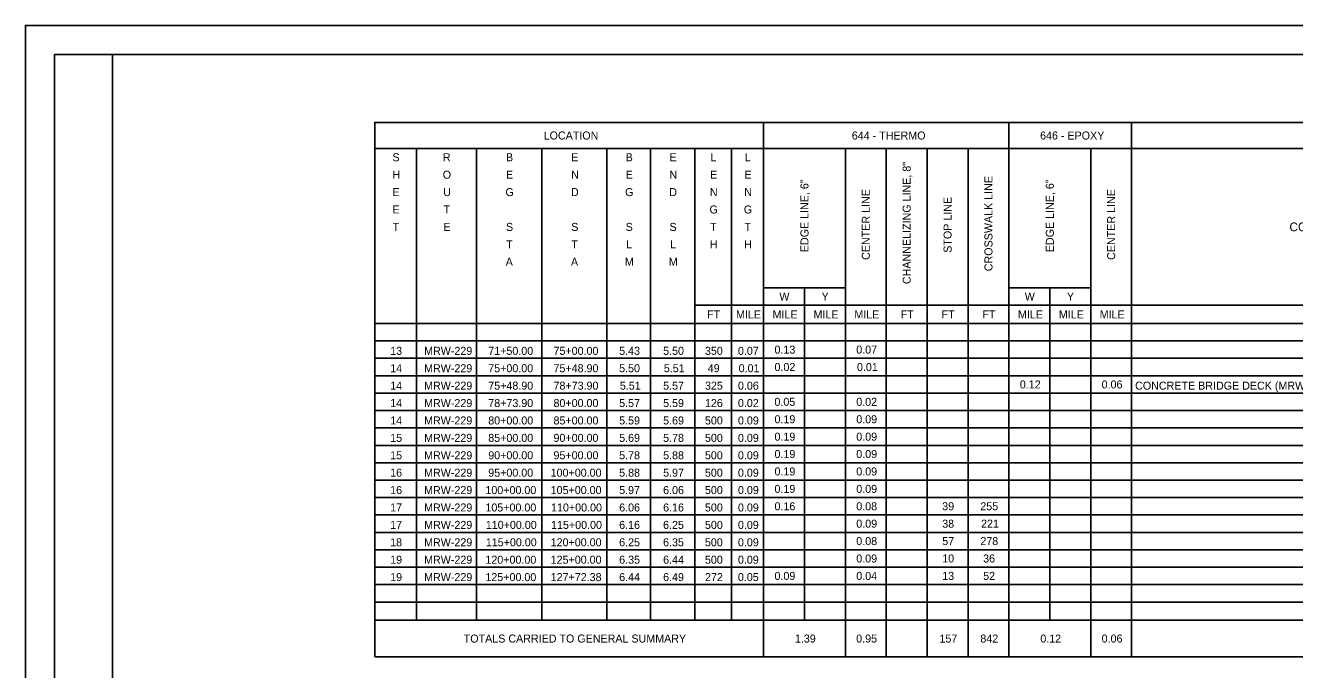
# Model space of a CAD drawing. Extents: x 0 to 34, y 0 to 22.
# Drawn here: x 0 to 21.88, y 10.9 to 22 of the extents above; entities that cross this region are included whole.
import ezdxf

# ---------------------------------------------------------------- set-up
doc = ezdxf.new("R2010")
doc.units = 0
for name, color, linetype in [('Default', 7, 'Continuous'), ('SH_Border', 7, 'Continuous'), ('SH_Cut_Line', 7, 'Continuous')]:
    doc.layers.add(name, color=color, linetype=linetype)

msp = doc.modelspace()

# ---------------------------------------------------------------- linework, layer by layer
at = {"layer": 'Default'}
for p, q in [((6.022, 20.327), (25.597, 20.327)), ((6.022, 20.327), (6.022, 11.117)), ((12.727, 20.327), (12.727, 11.117)), ((16.957, 20.327), (16.957, 11.117)), ((19.072, 20.327), (19.072, 11.117)), ((6.022, 19.877), (25.597, 19.877)), ((6.742, 19.877), (6.742, 11.747)), ((7.777, 19.877), (7.777, 11.747)), ((8.902, 19.877), (8.902, 11.747)), ((10.027, 19.877), (10.027, 11.747)), ((10.777, 19.877), (10.777, 11.747)), ((11.542, 19.877), (11.542, 11.747)), ((12.172, 19.877), (12.172, 11.747)), ((14.137, 19.877), (14.137, 11.117)), ((14.842, 19.877), (14.842, 11.117)), ((15.547, 19.877), (15.547, 11.117)), ((16.252, 19.877), (16.252, 11.117)), ((18.367, 19.877), (18.367, 11.117)), ((12.727, 17.477), (14.137, 17.477)), ((13.432, 17.477), (13.432, 11.747)), ((16.957, 17.477), (18.367, 17.477)), ((17.662, 17.477), (17.662, 11.747)), ((11.542, 17.177), (25.597, 17.177)), ((6.022, 16.862), (25.597, 16.862)), ((6.022, 16.562), (25.597, 16.562)), ((6.022, 16.262), (25.597, 16.262)), ((6.022, 15.962), (25.597, 15.962)), ((6.022, 15.662), (25.597, 15.662)), ((6.022, 15.362), (25.597, 15.362)), ((6.022, 15.062), (25.597, 15.062)), ((6.022, 14.762), (25.597, 14.762)), ((6.022, 14.462), (25.597, 14.462)), ((6.022, 14.162), (25.597, 14.162)), ((6.022, 13.862), (25.597, 13.862)), ((6.022, 13.562), (25.597, 13.562)), ((6.022, 13.262), (25.597, 13.262)), ((6.022, 12.962), (25.597, 12.962)), ((6.022, 12.662), (25.597, 12.662)), ((6.022, 12.362), (25.597, 12.362)), ((6.022, 12.062), (25.597, 12.062)), ((6.022, 11.747), (25.597, 11.747)), ((6.022, 11.117), (25.597, 11.117))]:
    msp.add_line(p, q, dxfattribs=at)
for points in [[(6.022, 20.327), (6.022, 20.327), (6.022, 20.027), (6.022, 20.027)], [(6.022, 20.327), (6.022, 20.327), (6.022, 20.027), (6.022, 20.027)], [(6.022, 20.327), (6.022, 20.327), (6.022, 20.027), (6.022, 20.027)], [(6.022, 20.327), (6.022, 20.327), (6.022, 20.027), (6.022, 20.027)], [(6.022, 20.327), (6.022, 20.327), (6.022, 20.027), (6.022, 20.027)], [(6.022, 20.327), (6.022, 20.327), (6.022, 20.027), (6.022, 20.027)], [(6.022, 20.327), (6.022, 20.327), (6.022, 20.027), (6.022, 20.027)], [(6.022, 20.327), (6.022, 20.327), (6.022, 20.027), (6.022, 20.027)], [(6.022, 20.327), (6.022, 20.327), (6.022, 20.027), (6.022, 20.027)], [(6.022, 20.327), (6.022, 20.327), (6.022, 20.012), (6.022, 20.012)], [(6.022, 20.327), (6.022, 20.327), (6.022, 20.027), (6.022, 20.027)], [(6.022, 20.327), (6.022, 20.327), (6.022, 20.027), (6.022, 20.027)], [(6.022, 20.327), (6.022, 20.327), (6.022, 20.027), (6.022, 20.027)], [(6.022, 20.327), (6.022, 20.327), (6.022, 20.027), (6.022, 20.027)], [(6.022, 20.327), (6.022, 20.327), (6.022, 20.027), (6.022, 20.027)], [(6.022, 20.327), (6.022, 20.327), (6.022, 20.027), (6.022, 20.027)], [(6.022, 20.327), (6.022, 20.327), (6.022, 20.027), (6.022, 20.027)], [(6.022, 20.327), (6.022, 20.327), (6.022, 20.027), (6.022, 20.027)], [(6.022, 20.327), (6.022, 20.327), (6.022, 20.027), (6.022, 20.027)], [(6.022, 20.327), (6.022, 20.327), (6.022, 20.027), (6.022, 20.027)], [(6.022, 20.327), (6.022, 20.327), (6.022, 20.027), (6.022, 20.027)], [(6.022, 20.327), (6.022, 20.327), (6.022, 20.027), (6.022, 20.027)], [(6.022, 20.327), (6.022, 20.327), (6.022, 20.027), (6.022, 20.027)], [(6.022, 20.327), (6.022, 20.327), (6.022, 20.027), (6.022, 20.027)], [(6.022, 20.327), (6.022, 20.327), (6.022, 20.027), (6.022, 20.027)], [(6.022, 20.327), (6.022, 20.327), (6.022, 20.027), (6.022, 20.027)], [(6.022, 20.327), (6.022, 20.327), (6.022, 20.012), (6.022, 20.012)]]:
    msp.add_lwpolyline(points, close=True, dxfattribs=at)
at = {"layer": 'SH_Border'}
for points in [[(0.5, 21.5), (1.5, 21.5), (1.5, 0.5), (0.5, 0.5)], [(1.5, 21.5), (33.5, 21.5), (33.5, 0.5), (1.5, 0.5)]]:
    msp.add_lwpolyline(points, close=True, dxfattribs=at)
at = {"layer": 'SH_Cut_Line'}
msp.add_lwpolyline([(0, 0), (34, 0), (34, 22), (0, 22)], close=True, dxfattribs=at)

# ---------------------------------------------------------------- texts
at = {"layer": 'Default'}
for s, height, p in [('LOCATION', 0.138, (8.935, 20.033)), ('644 - THERMO', 0.138, (14.248, 20.033)), ('646 - EPOXY', 0.138, (17.494, 20.033)), ('S', 0.138, (6.329, 19.658)), ('R', 0.138, (7.198, 19.658)), ('B', 0.138, (8.286, 19.658)), ('E', 0.138, (9.411, 19.658)), ('B', 0.138, (10.349, 19.658)), ('E', 0.138, (11.106, 19.658)), ('L', 0.138, (11.812, 19.658)), ('L', 0.138, (12.404, 19.658)), ('H', 0.138, (6.326, 19.358)), ('O', 0.138, (7.196, 19.358)), ('E', 0.138, (8.286, 19.358)), ('N', 0.138, (9.409, 19.358)), ('E', 0.138, (10.349, 19.358)), ('N', 0.138, (11.104, 19.358)), ('E', 0.138, (11.804, 19.358)), ('E', 0.138, (12.396, 19.358)), ('E', 0.138, (6.329, 19.058)), ('U', 0.138, (7.204, 19.058)), ('G', 0.138, (8.277, 19.058)), ('D', 0.138, (9.406, 19.058)), ('G', 0.138, (10.34, 19.058)), ('D', 0.138, (11.101, 19.058)), ('N', 0.138, (11.801, 19.058)), ('N', 0.138, (12.394, 19.058)), ('E', 0.138, (6.329, 18.758)), ('T', 0.138, (7.208, 18.758)), ('G', 0.138, (11.795, 18.758)), ('G', 0.138, (12.387, 18.758)), ('COMMENTS', 0.1518, (21.793, 18.451)), ('T', 0.138, (6.331, 18.458)), ('E', 0.138, (7.206, 18.458)), ('S', 0.138, (8.286, 18.458)), ('S', 0.138, (9.411, 18.458)), ('S', 0.138, (10.349, 18.458)), ('S', 0.138, (11.106, 18.458)), ('T', 0.138, (11.806, 18.458)), ('T', 0.138, (12.398, 18.458)), ('T', 0.138, (8.288, 18.158)), ('T', 0.138, (9.413, 18.158)), ('L', 0.138, (10.357, 18.158)), ('L', 0.138, (11.114, 18.158)), ('H', 0.138, (11.801, 18.158)), ('H', 0.138, (12.394, 18.158)), ('A', 0.138, (8.281, 17.858)), ('A', 0.138, (9.406, 17.858)), ('M', 0.138, (10.336, 17.858)), ('M', 0.138, (11.094, 17.858)), ('W', 0.138, (12.999, 17.258)), ('Y', 0.138, (13.727, 17.258)), ('W', 0.138, (17.229, 17.258)), ('Y', 0.138, (17.957, 17.258)), ('FT', 0.138, (11.753, 16.95)), ('MILE', 0.138, (12.252, 16.95)), ('MILE', 0.138, (12.882, 16.95)), ('MILE', 0.138, (13.587, 16.95)), ('MILE', 0.138, (14.292, 16.95)), ('FT', 0.138, (15.09, 16.95)), ('FT', 0.138, (15.795, 16.95)), ('FT', 0.138, (16.5, 16.95)), ('MILE', 0.138, (17.112, 16.95)), ('MILE', 0.138, (17.817, 16.95)), ('MILE', 0.138, (18.522, 16.95)), ('13', 0.138, (6.289, 16.322)), ('MRW-229', 0.138, (6.874, 16.322)), ('71+50.00', 0.138, (7.98, 16.322)), ('75+00.00', 0.138, (9.105, 16.322)), ('5.43', 0.138, (10.237, 16.322)), ('5.50', 0.138, (10.995, 16.322)), ('350', 0.138, (11.716, 16.322)), ('0.07', 0.138, (12.285, 16.322)), ('0.13', 0.138, (12.915, 16.343)), ('0.07', 0.138, (14.325, 16.343)), ('14', 0.138, (6.29, 16.022)), ('MRW-229', 0.138, (6.874, 16.022)), ('75+00.00', 0.138, (7.98, 16.022)), ('75+48.90', 0.138, (9.105, 16.022)), ('5.50', 0.138, (10.237, 16.022)), ('5.51', 0.138, (11.007, 16.022)), ('49', 0.138, (11.764, 16.022)), ('0.01', 0.138, (12.297, 16.022)), ('0.02', 0.138, (12.915, 16.043)), ('0.01', 0.138, (14.337, 16.043)), ('14', 0.138, (6.29, 15.722)), ('MRW-229', 0.138, (6.874, 15.722)), ('75+48.90', 0.138, (7.98, 15.722)), ('78+73.90', 0.138, (9.105, 15.722)), ('5.51', 0.138, (10.249, 15.722)), ('5.57', 0.138, (10.995, 15.722)), ('325', 0.138, (11.716, 15.722)), ('0.06', 0.138, (12.285, 15.722)), ('0.12', 0.138, (17.145, 15.743)), ('0.06', 0.138, (18.555, 15.743)), ('CONCRETE BRIDGE DECK (MRW-71-3.86, SR 229 OVER I-71)', 0.138, (19.132, 15.722)), ('14', 0.138, (6.29, 15.422)), ('MRW-229', 0.138, (6.874, 15.422)), ('78+73.90', 0.138, (7.98, 15.422)), ('80+00.00', 0.138, (9.105, 15.422)), ('5.57', 0.138, (10.237, 15.422)), ('5.59', 0.138, (10.995, 15.422)), ('126', 0.138, (11.716, 15.422)), ('0.02', 0.138, (12.285, 15.422)), ('0.05', 0.138, (12.914, 15.443)), ('0.02', 0.138, (14.325, 15.443)), ('14', 0.138, (6.29, 15.122)), ('MRW-229', 0.138, (6.874, 15.122)), ('80+00.00', 0.138, (7.98, 15.122)), ('85+00.00', 0.138, (9.105, 15.122)), ('5.59', 0.138, (10.237, 15.122)), ('5.69', 0.138, (10.995, 15.122)), ('500', 0.138, (11.716, 15.122)), ('0.09', 0.138, (12.285, 15.122)), ('0.19', 0.138, (12.915, 15.143)), ('0.09', 0.138, (14.325, 15.143)), ('15', 0.138, (6.289, 14.822)), ('MRW-229', 0.138, (6.874, 14.822)), ('85+00.00', 0.138, (7.98, 14.822)), ('90+00.00', 0.138, (9.105, 14.822)), ('5.69', 0.138, (10.237, 14.822)), ('5.78', 0.138, (10.995, 14.822)), ('500', 0.138, (11.716, 14.822)), ('0.09', 0.138, (12.285, 14.822)), ('0.19', 0.138, (12.915, 14.843)), ('0.09', 0.138, (14.325, 14.843)), ('MRW-229', 0.138, (6.874, 14.522)), ('90+00.00', 0.138, (7.98, 14.522)), ('95+00.00', 0.138, (9.105, 14.522)), ('5.78', 0.138, (10.237, 14.522)), ('5.88', 0.138, (10.995, 14.522)), ('500', 0.138, (11.716, 14.522)), ('0.09', 0.138, (12.285, 14.522)), ('0.19', 0.138, (12.915, 14.543)), ('0.09', 0.138, (14.325, 14.543)), ('15', 0.138, (6.289, 14.522)), ('16', 0.138, (6.289, 14.222)), ('MRW-229', 0.138, (6.874, 14.222)), ('95+00.00', 0.138, (7.98, 14.222)), ('100+00.00', 0.138, (9.056, 14.222)), ('5.88', 0.138, (10.237, 14.222)), ('5.97', 0.138, (10.995, 14.222)), ('500', 0.138, (11.716, 14.222)), ('0.09', 0.138, (12.285, 14.222)), ('0.19', 0.138, (12.915, 14.243)), ('0.09', 0.138, (14.325, 14.243)), ('16', 0.138, (6.289, 13.922)), ('MRW-229', 0.138, (6.874, 13.922)), ('100+00.00', 0.138, (7.931, 13.922)), ('105+00.00', 0.138, (9.056, 13.922)), ('5.97', 0.138, (10.237, 13.922)), ('6.06', 0.138, (10.995, 13.922)), ('500', 0.138, (11.716, 13.922)), ('0.09', 0.138, (12.285, 13.922)), ('0.19', 0.138, (12.915, 13.943)), ('0.09', 0.138, (14.325, 13.943)), ('17', 0.138, (6.289, 13.622)), ('MRW-229', 0.138, (6.874, 13.622)), ('105+00.00', 0.138, (7.931, 13.622)), ('110+00.00', 0.138, (9.063, 13.622)), ('6.06', 0.138, (10.237, 13.622)), ('6.16', 0.138, (10.995, 13.622)), ('500', 0.138, (11.716, 13.622)), ('0.09', 0.138, (12.285, 13.622)), ('0.16', 0.138, (12.915, 13.643)), ('0.08', 0.138, (14.325, 13.643)), ('39', 0.138, (15.807, 13.643)), ('255', 0.138, (16.463, 13.643)), ('17', 0.138, (6.289, 13.322)), ('MRW-229', 0.138, (6.874, 13.322)), ('110+00.00', 0.138, (7.938, 13.322)), ('115+00.00', 0.138, (9.063, 13.322)), ('6.16', 0.138, (10.237, 13.322)), ('6.25', 0.138, (10.994, 13.322)), ('500', 0.138, (11.716, 13.322)), ('0.09', 0.138, (12.285, 13.322)), ('0.09', 0.138, (14.325, 13.343)), ('38', 0.138, (15.807, 13.343)), ('221', 0.138, (16.476, 13.343)), ('18', 0.138, (6.289, 13.022)), ('MRW-229', 0.138, (6.874, 13.022)), ('115+00.00', 0.138, (7.938, 13.022)), ('120+00.00', 0.138, (9.056, 13.022)), ('6.25', 0.138, (10.237, 13.022)), ('6.35', 0.138, (10.994, 13.022)), ('500', 0.138, (11.716, 13.022)), ('0.09', 0.138, (12.285, 13.022)), ('0.08', 0.138, (14.325, 13.043)), ('57', 0.138, (15.807, 13.043)), ('278', 0.138, (16.464, 13.043)), ('19', 0.138, (6.289, 12.722)), ('MRW-229', 0.138, (6.874, 12.722)), ('120+00.00', 0.138, (7.931, 12.722)), ('125+00.00', 0.138, (9.056, 12.722)), ('6.35', 0.138, (10.237, 12.722)), ('6.44', 0.138, (10.995, 12.722)), ('500', 0.138, (11.716, 12.722)), ('0.09', 0.138, (12.285, 12.722)), ('0.09', 0.138, (14.325, 12.743)), ('10', 0.138, (15.807, 12.743)), ('36', 0.138, (16.512, 12.743)), ('19', 0.138, (6.289, 12.422)), ('MRW-229', 0.138, (6.874, 12.422)), ('125+00.00', 0.138, (7.931, 12.422)), ('127+72.38', 0.138, (9.056, 12.422)), ('6.44', 0.138, (10.237, 12.422)), ('6.49', 0.138, (10.995, 12.422)), ('272', 0.138, (11.717, 12.422)), ('0.05', 0.138, (12.284, 12.422)), ('0.09', 0.138, (12.915, 12.443)), ('0.04', 0.138, (14.325, 12.443)), ('13', 0.138, (15.807, 12.443)), ('52', 0.138, (16.513, 12.443)), ('TOTALS CARRIED TO GENERAL SUMMARY', 0.138, (7.557, 11.363)), ('1.39', 0.138, (13.267, 11.363)), ('0.95', 0.138, (14.324, 11.363)), ('157', 0.138, (15.759, 11.363)), ('842', 0.138, (16.464, 11.363)), ('0.12', 0.138, (17.498, 11.363)), ('0.06', 0.138, (18.555, 11.363))]:
    msp.add_text(s, height=height, dxfattribs=at).set_placement(p)
for s, p in [('CHANNELIZING LINE, 8"', (15.263, 17.541)), ('EDGE LINE, 6"', (13.501, 18.091)), ('CROSSWALK LINE', (16.673, 17.763)), ('EDGE LINE, 6"', (17.731, 18.091)), ('CENTER LINE', (14.558, 17.958)), ('CENTER LINE', (18.788, 17.958)), ('STOP LINE', (15.968, 18.081))]:
    msp.add_text(s, height=0.138, rotation=90, dxfattribs=at).set_placement(p)

doc.saveas('drawing.dxf')
